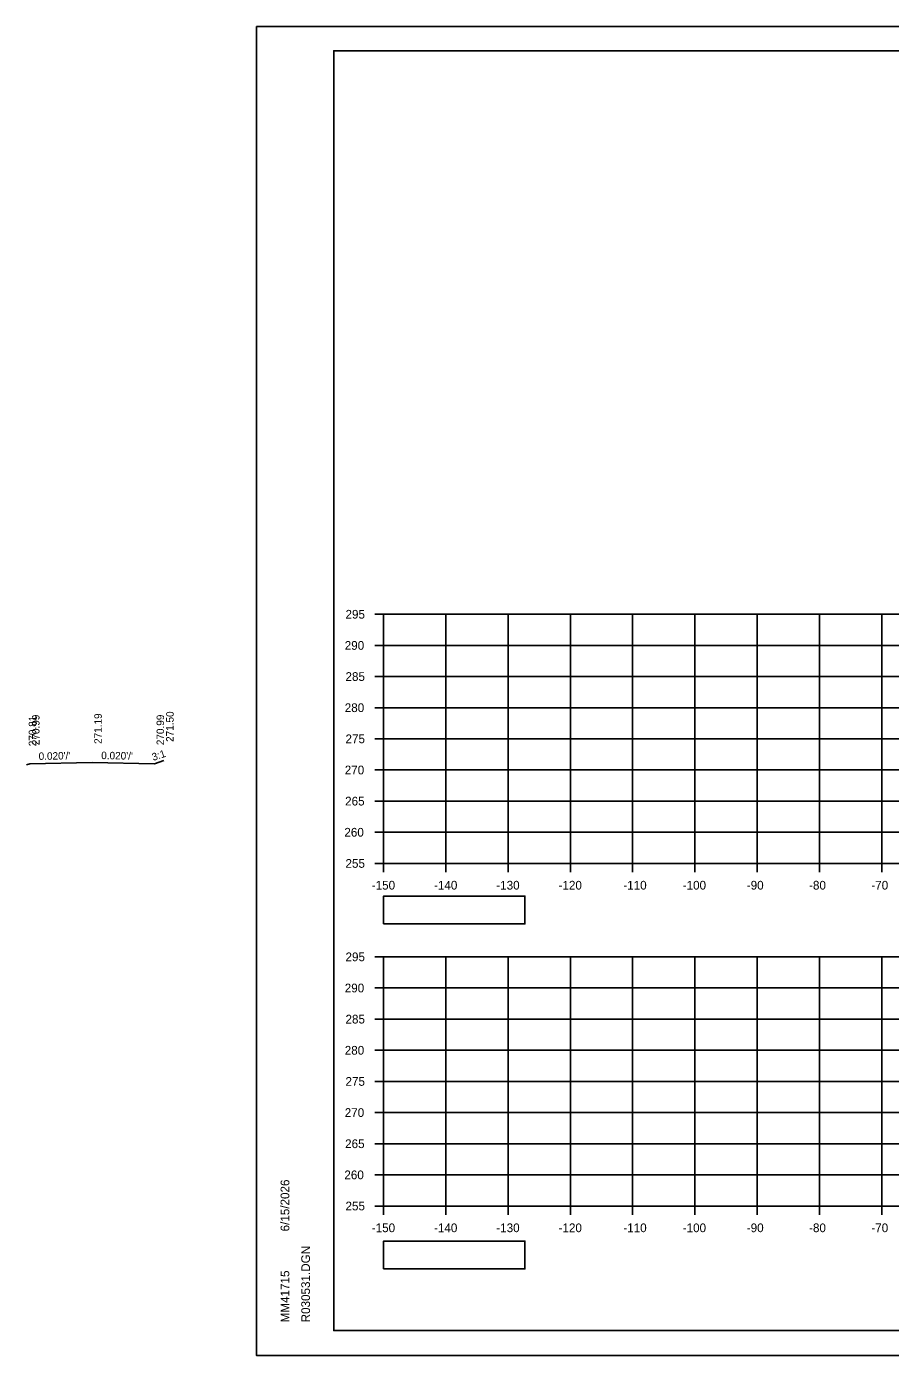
# Model space of a CAD drawing. Extents: x 285 to 4233, y -659 to 3710.
# Drawn here: x 3863.1 to 4001.8, y 60.8 to 274.1 of the extents above; entities that cross this region are included whole.
import ezdxf

# ---------------------------------------------------------------- set-up
doc = ezdxf.new("R2010")
doc.units = 0
for name, color, linetype in [('R_Axis', 7, 'Continuous'), ('R_Axis Annot', 7, 'Continuous'), ('R_Border', 7, 'Continuous'), ('R_Fin Surface', 7, 'Continuous'), ('R_Grid', 7, 'Continuous'), ('R_No Plot', 7, 'Continuous'), ('R_Xsect Elev', 7, 'Continuous'), ('R_Xsect Slope', 7, 'Continuous')]:
    doc.layers.add(name, color=color, linetype=linetype)

msp = doc.modelspace()

# ---------------------------------------------------------------- linework, layer by layer
at = {"layer": 'R_Axis'}
for p, q in [((3918.98, 179.76), (3920.38, 179.76)), ((3920.38, 139.76), (3920.38, 179.76)), ((3918.98, 174.76), (3920.38, 174.76)), ((3918.98, 169.76), (3920.38, 169.76)), ((3918.98, 164.76), (3920.38, 164.76)), ((3918.98, 159.76), (3920.38, 159.76)), ((3918.98, 154.76), (3920.38, 154.76)), ((3918.98, 149.76), (3920.38, 149.76)), ((3918.98, 144.76), (3920.38, 144.76)), ((3918.98, 139.76), (3920.38, 139.76)), ((3920.38, 139.76), (4220.38, 139.76)), ((3920.38, 138.36), (3920.38, 139.76)), ((3930.38, 138.36), (3930.38, 139.76)), ((3940.38, 138.36), (3940.38, 139.76)), ((3950.38, 138.36), (3950.38, 139.76)), ((3960.38, 138.36), (3960.38, 139.76)), ((3970.38, 138.36), (3970.38, 139.76)), ((3980.38, 138.36), (3980.38, 139.76)), ((3990.38, 138.36), (3990.38, 139.76)), ((4000.38, 138.36), (4000.38, 139.76)), ((3918.98, 124.76), (3920.38, 124.76)), ((3920.38, 84.76), (3920.38, 124.76)), ((3918.98, 119.76), (3920.38, 119.76)), ((3918.98, 114.76), (3920.38, 114.76)), ((3918.98, 109.76), (3920.38, 109.76)), ((3918.98, 104.76), (3920.38, 104.76)), ((3918.98, 99.76), (3920.38, 99.76)), ((3918.98, 94.76), (3920.38, 94.76)), ((3918.98, 89.76), (3920.38, 89.76)), ((3918.98, 84.76), (3920.38, 84.76)), ((3920.38, 84.76), (4220.38, 84.76)), ((3920.38, 83.36), (3920.38, 84.76)), ((3930.38, 83.36), (3930.38, 84.76)), ((3940.38, 83.36), (3940.38, 84.76)), ((3950.38, 83.36), (3950.38, 84.76)), ((3960.38, 83.36), (3960.38, 84.76)), ((3970.38, 83.36), (3970.38, 84.76)), ((3980.38, 83.36), (3980.38, 84.76)), ((3990.38, 83.36), (3990.38, 84.76)), ((4000.38, 83.36), (4000.38, 84.76))]:
    msp.add_line(p, q, dxfattribs=at)
at = {"layer": 'R_Axis Annot'}
for points in [[(3920.38, 130.05), (3943.08, 130.05), (3943.08, 134.52), (3920.38, 134.52)], [(3920.38, 74.65), (3943.08, 74.65), (3943.08, 79.12), (3920.38, 79.12)]]:
    msp.add_lwpolyline(points, close=True, dxfattribs=at)
at = {"layer": 'R_Border'}
for p, q in [((3912.38, 270.22), (4228.56, 270.22)), ((3912.38, 64.76), (3912.38, 270.22)), ((3912.38, 64.76), (3912.38, 64.76)), ((4228.56, 64.76), (3912.38, 64.76))]:
    msp.add_line(p, q, dxfattribs=at)
at = {"layer": 'R_Fin Surface'}
msp.add_lwpolyline([(3863.05, 155.57), (3863.58, 155.74), (3873.58, 155.94), (3883.58, 155.74), (3885.12, 156.26)], dxfattribs=at)
at = {"layer": 'R_Grid'}
for p, q in [((3920.38, 179.76), (4220.38, 179.76)), ((3920.38, 139.76), (3920.38, 179.76)), ((3930.38, 139.76), (3930.38, 179.76)), ((3940.38, 139.76), (3940.38, 179.76)), ((3950.38, 139.76), (3950.38, 179.76)), ((3960.38, 139.76), (3960.38, 179.76)), ((3970.38, 139.76), (3970.38, 179.76)), ((3980.38, 139.76), (3980.38, 179.76)), ((3990.38, 139.76), (3990.38, 179.76)), ((4000.38, 139.76), (4000.38, 179.76)), ((3920.38, 174.76), (4220.38, 174.76)), ((3920.38, 169.76), (4220.38, 169.76)), ((3920.38, 164.76), (4220.38, 164.76)), ((3920.38, 159.76), (4220.38, 159.76)), ((3920.38, 154.76), (4220.38, 154.76)), ((3920.38, 149.76), (4220.38, 149.76)), ((3920.38, 144.76), (4220.38, 144.76)), ((3920.38, 139.76), (4220.38, 139.76)), ((3920.38, 124.76), (4220.38, 124.76)), ((3920.38, 84.76), (3920.38, 124.76)), ((3930.38, 84.76), (3930.38, 124.76)), ((3940.38, 84.76), (3940.38, 124.76)), ((3950.38, 84.76), (3950.38, 124.76)), ((3960.38, 84.76), (3960.38, 124.76)), ((3970.38, 84.76), (3970.38, 124.76)), ((3980.38, 84.76), (3980.38, 124.76)), ((3990.38, 84.76), (3990.38, 124.76)), ((4000.38, 84.76), (4000.38, 124.76)), ((3920.38, 119.76), (4220.38, 119.76)), ((3920.38, 114.76), (4220.38, 114.76)), ((3920.38, 109.76), (4220.38, 109.76)), ((3920.38, 104.76), (4220.38, 104.76)), ((3920.38, 99.76), (4220.38, 99.76)), ((3920.38, 94.76), (4220.38, 94.76)), ((3920.38, 89.76), (4220.38, 89.76)), ((3920.38, 84.76), (4220.38, 84.76))]:
    msp.add_line(p, q, dxfattribs=at)
at = {"layer": 'R_No Plot'}
for p, q in [((3899.98, 274.11), (4233.31, 274.11)), ((3899.98, 60.78), (4233.31, 60.78))]:
    msp.add_line(p, q, dxfattribs=at)
for points in [[(3899.97, 274.11), (4233.31, 274.11), (4233.31, 60.77), (3899.97, 60.77)], [(4146.3, 270.22), (4165.92, 270.22), (4165.92, 260.34), (4182.03, 260.34), (4205.23, 260.34), (4205.35, 232.18), (4228.56, 232.18), (4228.56, 64.76), (3912.38, 64.76), (3912.38, 270.22)]]:
    msp.add_lwpolyline(points, close=True, dxfattribs=at)

# ---------------------------------------------------------------- texts
at = {"layer": 'R_Axis Annot'}
for s, p in [('295', (3914.27, 179.06)), ('290', (3914.15, 174.06)), ('285', (3914.27, 169.06)), ('280', (3914.15, 164.06)), ('275', (3914.27, 159.06)), ('270', (3914.15, 154.06)), ('265', (3914.21, 149.06)), ('260', (3914.09, 144.06)), ('255', (3914.27, 139.06)), ('-150', (3918.49, 135.56)), ('-140', (3928.49, 135.56)), ('-130', (3938.49, 135.56)), ('-120', (3948.49, 135.56)), ('-110', (3958.89, 135.56)), ('-100', (3968.43, 135.56)), ('-90', (3978.72, 135.56)), ('-80', (3988.72, 135.56)), ('-70', (3998.72, 135.56)), ('295', (3914.27, 124.06)), ('290', (3914.15, 119.06)), ('285', (3914.27, 114.06)), ('280', (3914.15, 109.06)), ('275', (3914.27, 104.06)), ('270', (3914.15, 99.06)), ('265', (3914.21, 94.06)), ('260', (3914.09, 89.06)), ('255', (3914.27, 84.06)), ('-150', (3918.49, 80.56)), ('-140', (3928.49, 80.56)), ('-130', (3938.49, 80.56)), ('-120', (3948.49, 80.56)), ('-110', (3958.89, 80.56)), ('-100', (3968.43, 80.56)), ('-90', (3978.72, 80.56)), ('-80', (3988.72, 80.56)), ('-70', (3998.72, 80.56))]:
    msp.add_text(s, height=1.4, dxfattribs=at).set_placement(p)
at = {"layer": 'R_Border'}
for s, p in [('6/15/2026', (3905.25, 80.68)), ('R030531.DGN', (3908.57, 66.08)), ('MM41715', (3905.25, 66.08))]:
    msp.add_text(s, height=1.4, rotation=90, dxfattribs=at).set_placement(p)
at = {"layer": 'R_Xsect Elev'}
for s, p in [('270.81', (3864.6, 158.57)), ('270.99', (3865.13, 158.74)), ('271.19', (3875.13, 158.94)), ('270.99', (3885.13, 158.74)), ('271.50', (3886.67, 159.26))]:
    msp.add_text(s, height=1.2, rotation=90, dxfattribs=at).set_placement(p)
at = {"layer": 'R_Xsect Slope'}
for s, rotation, p in [('3:1', 18.4349, (3883.4, 156.21)), ("0.020'/'", 1.1458, (3865, 156.37)), ("0.020'/'", 358.8542, (3875.03, 156.51))]:
    msp.add_text(s, height=1.2, rotation=rotation, dxfattribs=at).set_placement(p)

doc.saveas('drawing.dxf')
